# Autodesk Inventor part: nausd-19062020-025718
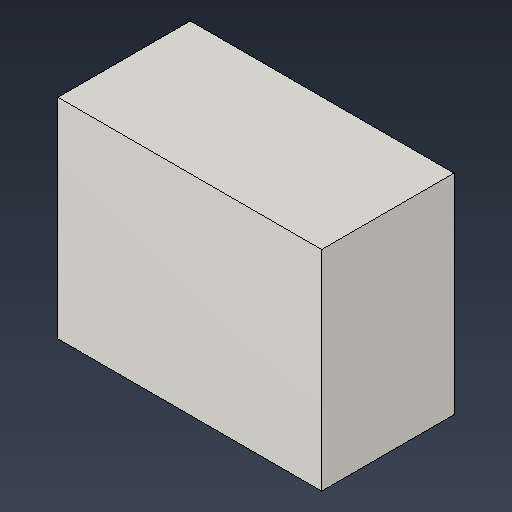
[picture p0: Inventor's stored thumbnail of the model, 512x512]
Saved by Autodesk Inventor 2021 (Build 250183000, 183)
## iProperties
Created: 2020-06
Part Number: nausd-19062020-025718
Material: Ocel
Document SubType Name: Modelování
Designer: naus
Density: 7.85 g/cm^3
Sheet Metal Rule: Default_mm
Appearance: Ocel
Mass: 24.7213 g
Surface Area: 13.4444 cm^2
Volume: 3.14921 cm^3
a12_Nazev_soucasti_ks: plech
a20_Barva: Ocel
a21_Hustota: NaN kg/m^3
a22_Material: Ocel
a23_Polozka_slouceni: s
Date Saved: 19062020
Saved By: nausd
Time Saved: 025718
Volume_Fluid_Category: NO
Author: naus
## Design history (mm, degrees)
sketch "Náčrt1"
  geometry: L1 (-9.044, 7.211)-(10.878, 7.211); L2 (10.878, 7.211)-(10.878, -8.596); L3 (10.878, -8.596)-(-9.044, -8.596); L4 (-9.044, -8.596)-(-9.044, 7.211); 1 further point
  constraints: 8 end point, 2 parallel, 1 horizontal, 1 perpendicular
extrude "Vysunutí1" new body sketch "Náčrt1" distance "d0" = 10; taper "d1" = 0 deg
node "Těleso1"
other parameters: "Tloušťka" = 5 (derived), "KSoučinitel" = 4.4, "PoloměrOhybu" = 5 (= Tloušťka), "ŠířkaVýštipu" = 5 (= Tloušťka), "HloubkaVýštipu" = 2.5 (= 0.5 x Tloušťka), "MezeraVystřižení" = 0.01, "PřechodovýPoloměr" = 5 (= PoloměrOhybu), "VelikostJacobihoPoloměru" = 5 (= PoloměrOhybu), "VelikostMezery" = 5 (= Tloušťka)
